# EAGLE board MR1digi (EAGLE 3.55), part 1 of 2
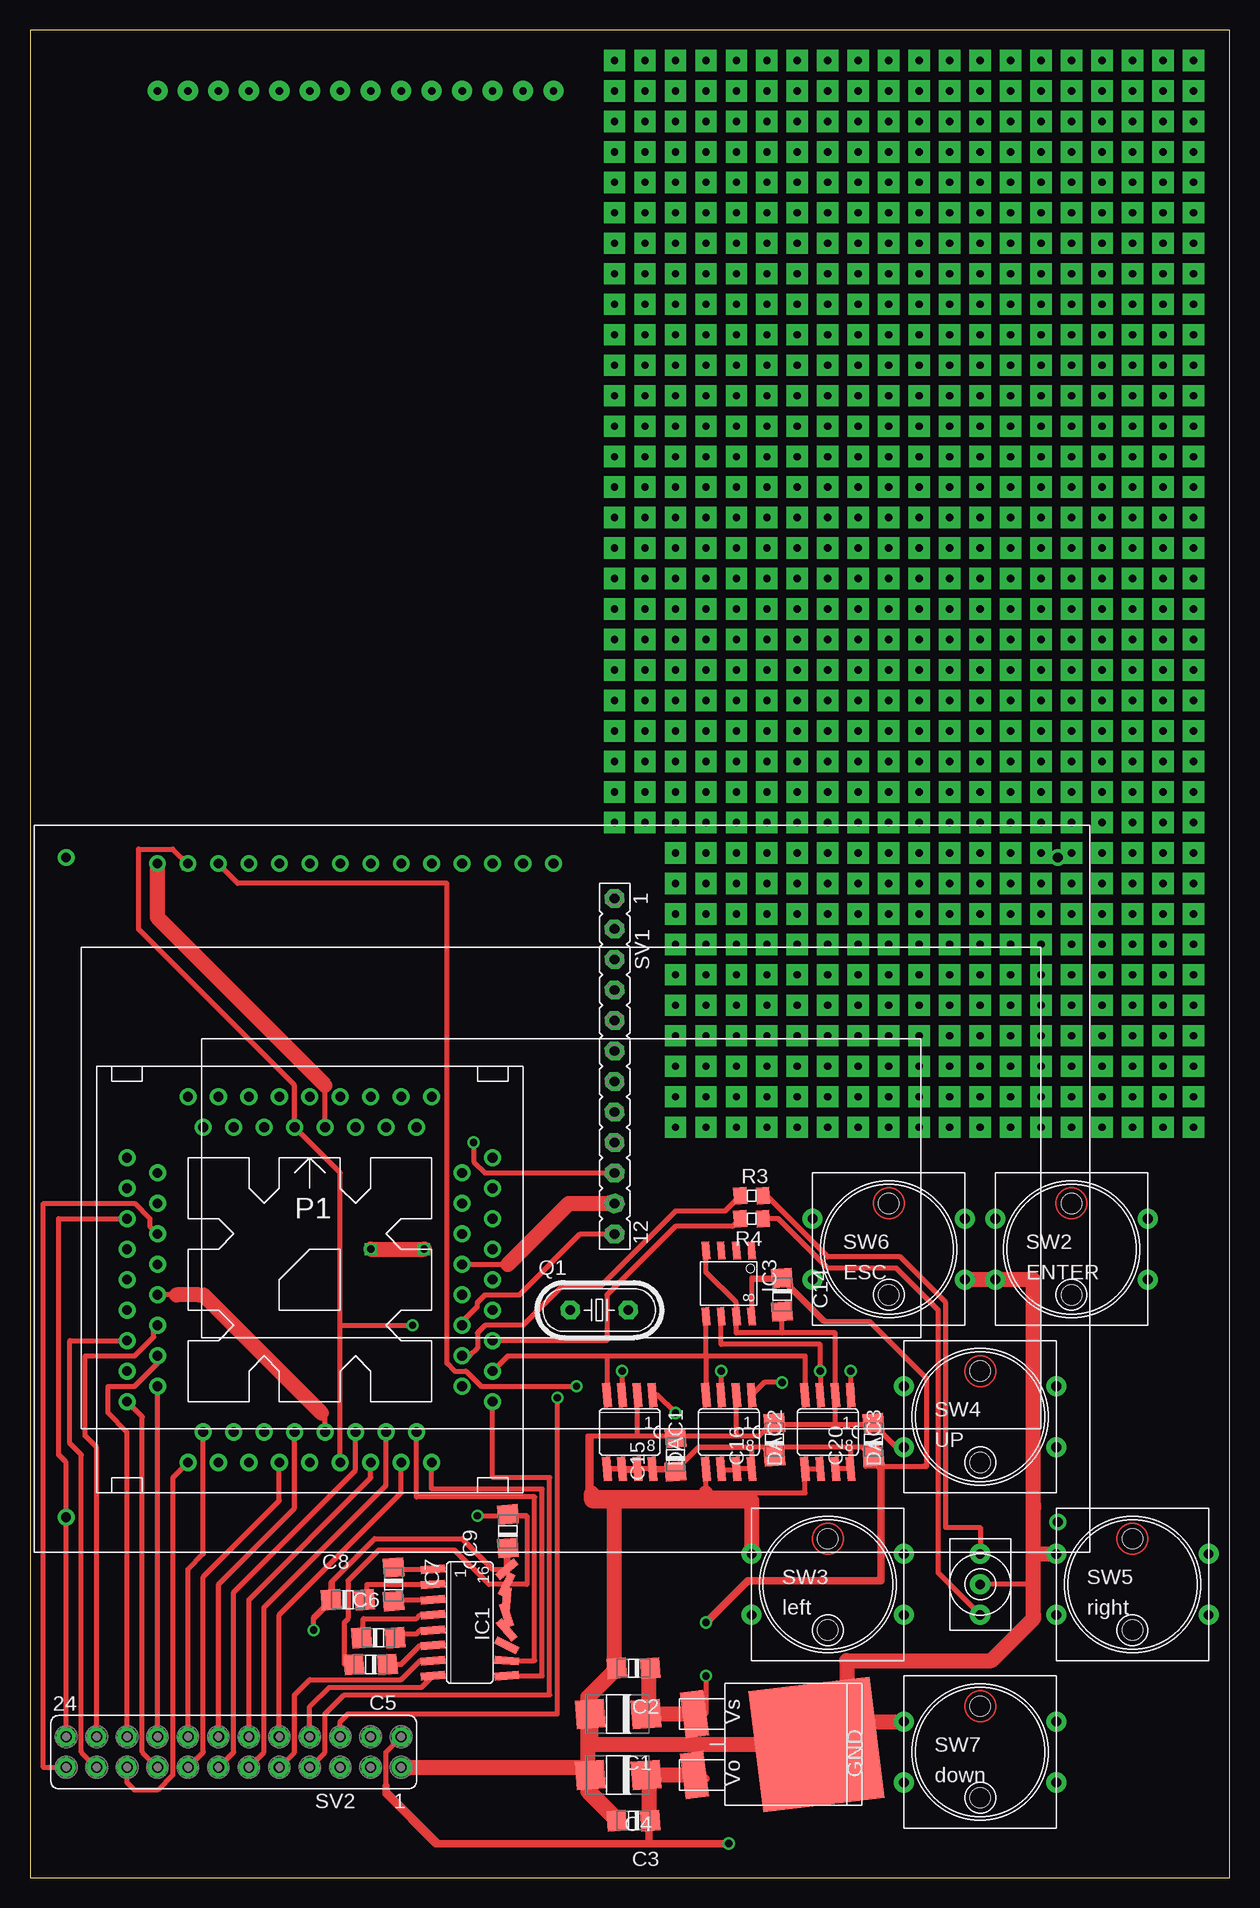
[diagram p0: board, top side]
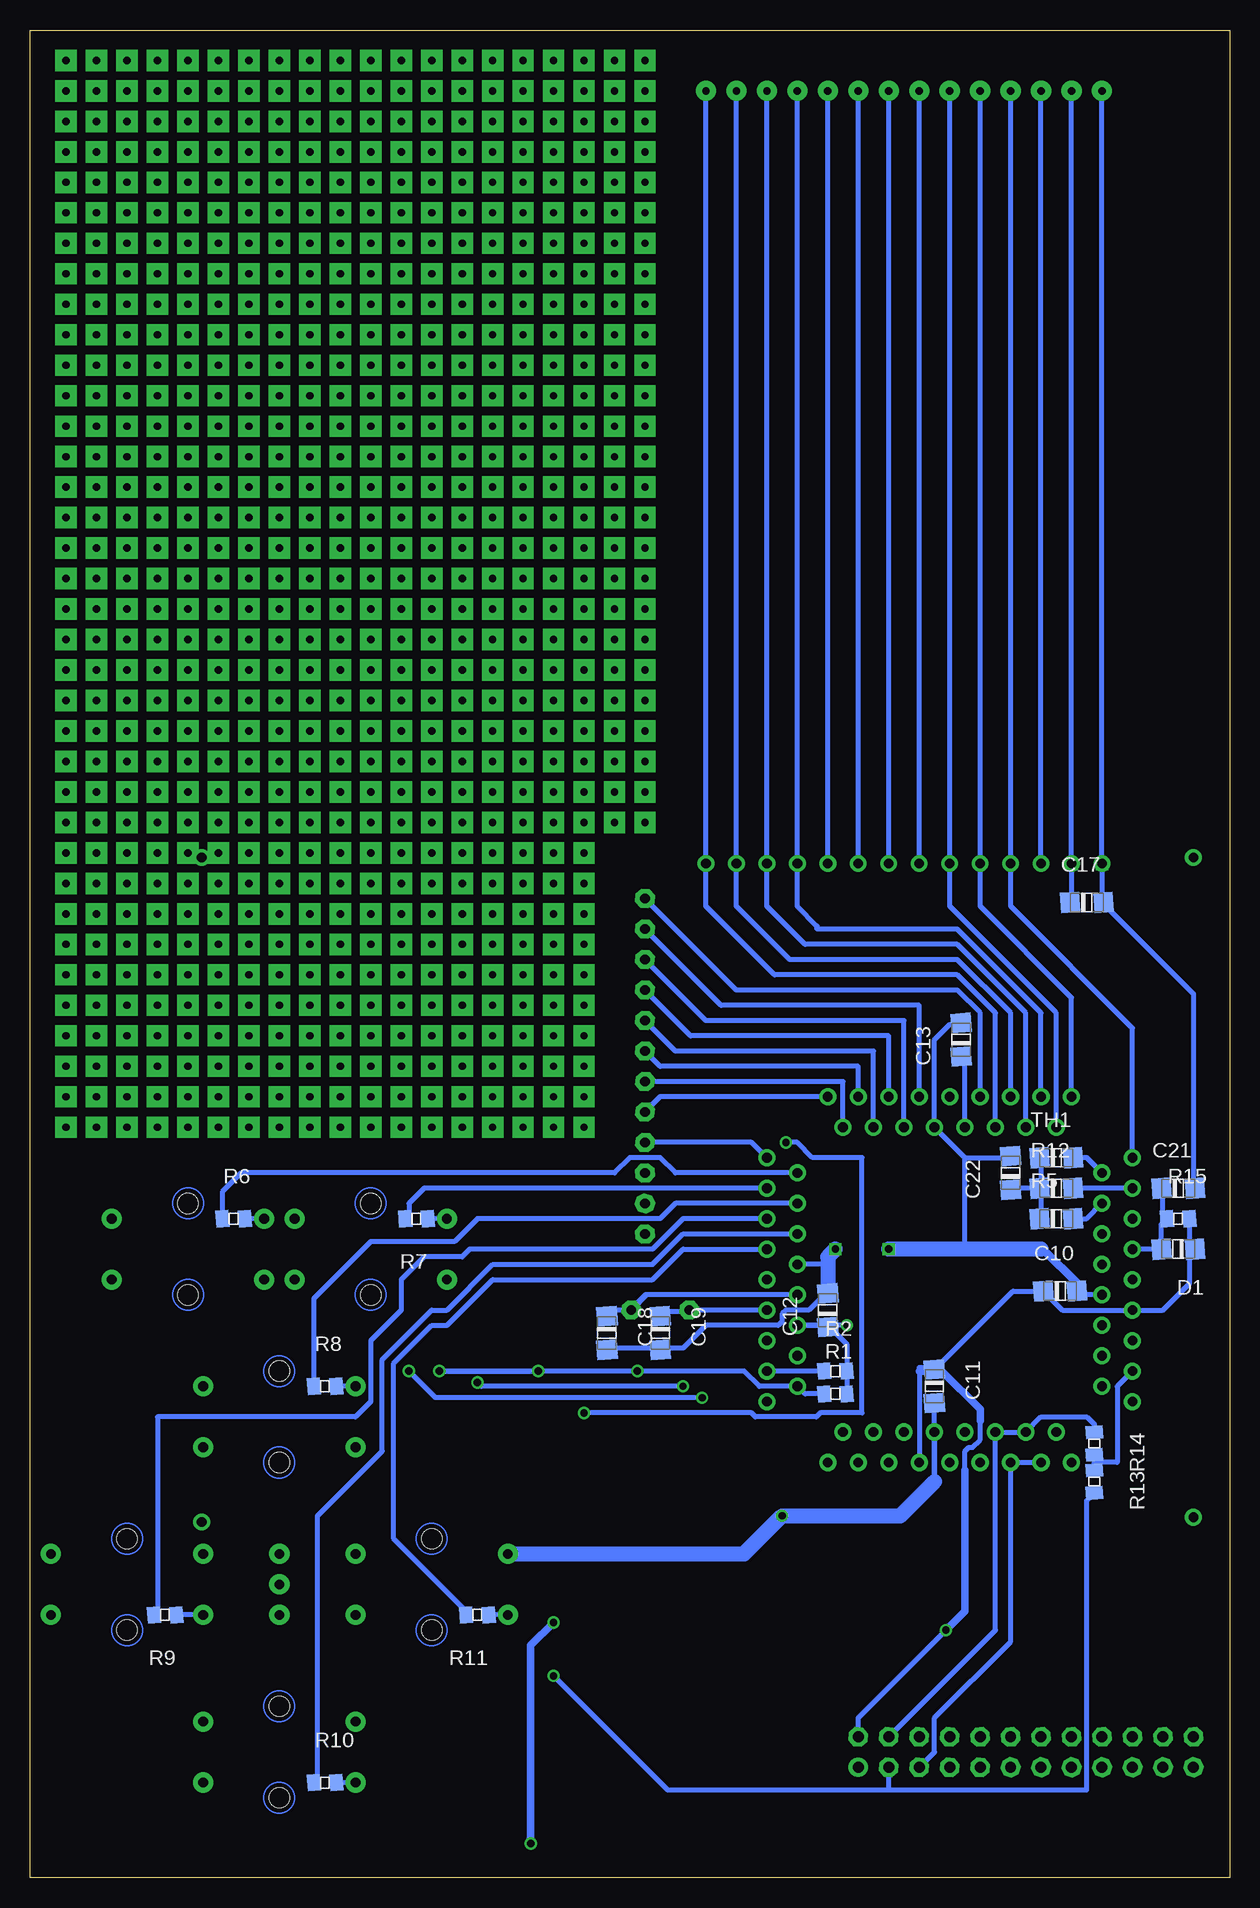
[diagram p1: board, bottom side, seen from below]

Size 100 x 153.98 mm. Coordinates in mm from the lower left corner, seen from the top.
Outline: 0,0 100,0 100,153.98 0,153.98 0,0
Copper layers used: Top, Bottom

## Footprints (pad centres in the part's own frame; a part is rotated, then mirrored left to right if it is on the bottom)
32 = smd 2.388 x 2.388 rotated 4.4:  2.337,0 | smd 2.388 x 2.388 rotated 4.3:  -2.311,0
16 = smd 1.6 x 1.702 rotated 4.4:  1.397,0 | smd 1.6 x 1.702 rotated 4.3:  -1.397,0
08 = smd 0.66 x 2.032 rotated 4.3:  -1.905,-3.073 | smd 0.66 x 2.032 rotated 4.9:  -1.905,3.073 | smd 0.66 x 2.032 rotated 4.4:  -0.635,-3.073 | smd 0.66 x 2.032 rotated 4.5:  0.635,-3.073 | smd 0.66 x 2.032 rotated 4.8:  -0.635,3.073 | smd 0.66 x 2.032 rotated 4.7:  0.635,3.073;  1.905,3.073 | smd 0.66 x 2.032 rotated 4.6:  1.905,-3.073
16' = smd 0.66 x 2.032 rotated 4.3:  -4.445,-3.073;  3.175,3.073 | smd 0.66 x 2.032 rotated 139.3:  -4.445,3.073 | smd 0.66 x 2.032 rotated 4.4:  -3.175,-3.073 | smd 0.66 x 2.032 rotated 4.5:  -1.905,-3.073 | smd 0.66 x 2.032 rotated 116.8:  -3.175,3.073 | smd 0.66 x 2.032 rotated 94.3:  -1.905,3.073 | smd 0.66 x 2.032 rotated 4.6:  -0.635,-3.073 | smd 0.66 x 2.032 rotated 71.8:  -0.635,3.073 | smd 0.66 x 2.032 rotated 4.7:  0.635,-3.073;  1.905,-3.073 | smd 0.66 x 2.032 rotated 49.3:  0.635,3.073 | smd 0.66 x 2.032 rotated 4.8:  3.175,-3.073 | smd 0.66 x 2.032 rotated 26.8:  1.905,3.073 | smd 0.66 x 2.032 rotated 4.9:  4.445,-3.073 | smd 0.66 x 2.032 rotated 5:  4.445,3.073
D_TO22 = smd 1.93 x 3.81 rotated 97:  1.27,-6.35;  6.35,-6.35 | smd 10.16 x 10.16 rotated 97:  3.81,3.81
8 = smd 0.61 x 1.524 rotated 4.3:  -1.27,-2.743 | smd 0.61 x 1.524 rotated 4.9:  -1.27,2.743 | smd 0.61 x 1.524 rotated 4.4:  0,-2.743 | smd 0.61 x 1.524 rotated 4.5:  1.27,-2.743 | smd 0.61 x 1.524 rotated 4.8:  0,2.743 | smd 0.61 x 1.524 rotated 4.7:  1.27,2.743;  2.54,2.743 | smd 0.61 x 1.524 rotated 4.6:  2.54,-2.743
-1604A = drill 0.813 pad 1.397 round: 0 -10.795,27.051; 1 -8.255,27.051; 2 -5.715,27.051; 3 -3.175,27.051; 4 -0.635,27.051; 5 -41.275,27.559; 6 -41.275,-27.432; 7 41.402,-27.813; 8 41.402,27.559;  -33.655,27.051;  -31.115,27.051;  -28.575,27.051;  -26.035,27.051;  -23.495,27.051;  -20.955,27.051;  -18.415,27.051;  -15.875,27.051;  -13.335,27.051
49U-V = drill 0.813 pad 1.6 octagon:  -2.413,0;  2.413,0
05 = smd 1.092 x 1.397 rotated 4.4:  0.94,0 | smd 1.092 x 1.397 rotated 4.3:  -0.94,0
12 = drill 0.813 pad 1.6 octagon:  -13.97,0;  -11.43,0;  -8.89,0;  -6.35,0;  -3.81,0;  -1.27,0;  1.27,0;  3.81,0;  6.35,0;  8.89,0;  11.43,0;  13.97,0
12-2 = drill 0.914 pad 1.6 round:  -13.97,1.27 | drill 0.914 pad 1.6 octagon:  -13.97,-1.27;  -11.43,1.27;  -11.43,-1.27;  -8.89,1.27;  -8.89,-1.27;  -6.35,1.27;  -6.35,-1.27;  -3.81,1.27;  -3.81,-1.27;  -1.27,1.27;  -1.27,-1.27;  1.27,1.27;  1.27,-1.27;  3.81,1.27;  3.81,-1.27;  6.35,1.27;  6.35,-1.27;  8.89,1.27;  8.89,-1.27;  11.43,1.27;  11.43,-1.27;  13.97,1.27;  13.97,-1.27
03 = drill 0.813 pad 1.676 round:  -2.54,0;  0,0;  2.54,0
MR1 = drill 0.813 pad 1.676 round:  -5.08,2.54;  -5.08,-2.54;  7.62,-2.54;  7.62,2.54 | hole 1.676: 1.27,3.81; 1.27,-3.81
F-68 = drill 0.813 pad 1.422 round: 0 -15.24,10.16; 0 -15.24,-2.54; 0 -6.35,-12.7; 0 6.35,-12.7; 0 15.24,-2.54; 0 15.24,10.16; 1 -12.7,8.89; 1 -12.7,-3.81; 1 -5.08,-15.24; 1 7.62,-15.24; 1 12.7,-1.27; 1 10.16,15.24; 2 -15.24,7.62; 2 -15.24,-5.08; 2 -3.81,-12.7; 2 8.89,-12.7; 2 15.24,0; 2 8.89,12.7; 3 -12.7,6.35; 3 -12.7,-6.35; 3 -2.54,-15.24; 3 10.16,-15.24; 3 12.7,1.27; 3 7.62,15.24; 4 -15.24,5.08; 4 -15.24,-7.62; 4 -1.27,-12.7; 4 15.24,-10.16; 4 15.24,2.54; 4 6.35,12.7; 5 -12.7,3.81; 5 -12.7,-8.89; 5 0,-15.24; 5 12.7,-8.89; 5 12.7,3.81; 5 5.08,15.24; 6 -15.24,2.54; 6 -15.24,-10.16; 6 1.27,-12.7; 6 15.24,-7.62; 6 15.24,5.08; 6 3.81,12.7; 7 -12.7,1.27; 7 -10.16,-15.24; 7 2.54,-15.24; 7 12.7,-6.35; 7 12.7,6.35; 7 2.54,15.24; 8 -15.24,0; 8 -8.89,-12.7; 8 3.81,-12.7; 8 15.24,-5.08; 8 15.24,7.62; 8 1.27,12.7; 9 -12.7,-1.27; 9 -7.62,-15.24; 9 5.08,-15.24; 9 12.7,-3.81; 9 12.7,8.89;  0,15.24;  -1.27,12.7;  -2.54,15.24;  -3.81,12.7;  -5.08,15.24;  -6.35,12.7;  -7.62,15.24;  -8.89,12.7;  -10.16,15.24

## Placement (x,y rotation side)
C1  100u  [32]  49.05,13.65 180 top
C2  100n  [16]  50.32,17.46 180 top
C3  100n  [16]  50.32,4.76 180 top
C4  100u  [32]  49.05,8.57 180 top
C5  100n  [16]  28.41,17.77 180 top
C6  100n  [16]  29.04,20 0 top
C7  100n  [16]  30.31,24.44 270 top
C8  100n  [16]  26.5,23.17 0 top
C9  100n  [16]  39.84,28.89 90 top
C10  100n  [16]  14.12,48.89 0 bottom
C11  100n  [16]  24.6,40.95 270 bottom
C12  100n  [16]  33.49,47.3 90 bottom
C13  100n  [16]  22.38,69.84 90 bottom
C14  100n  [16]  62.7,48.57 270 top
C15  100n  [16]  53.81,35.24 90 top
C16  100n  [16]  62.06,36.51 90 top
C17  100n  [16]  11.9,81.28 0 bottom
C18  30p  [16]  51.91,45.4 270 bottom
C19  30p  [16]  47.46,45.4 270 bottom
C20  100n  [16]  70.32,36.51 90 top
C21  100n  [16]  4.28,57.46 0 bottom
C22  330n  [16]  18.25,58.73 90 bottom
D1  DIODE_3216  [16]  4.28,52.38 180 bottom
DAC1  MAX517BCSA  [08]  50,37.14 180 top
DAC2  MAX517BCSA  [08]  58.25,37.14 180 top
DAC3  MAX517BCSA  [08]  66.51,37.14 180 top
IC1  MAX232CSE  [16']  36.66,21.27 270 top
IC2  MC7805CD2T  [D_TO22]  61.75,14.92 270 top
IC3  24LC04B/08  [8]  58.89,49.53 180 top
LCD1  PC-1604A  [-1604A]  44.28,57.46 0 top
Q1  32MHz  [49U-V]  47.46,47.3 0 top
R1  10k  [05]  32.85,40.32 0 bottom
R2  10k  [05]  32.85,42.22 0 bottom
R3  100  [05]  60.16,54.92 0 top
R4  100  [05]  60.16,56.83 180 top
R5  400  [16]  14.44,54.92 0 bottom
R6  100  [05]  83.02,54.92 0 bottom
R7  100  [05]  67.78,54.92 180 bottom
R8  100  [05]  75.4,40.95 0 bottom
R9  100  [05]  88.73,21.9 180 bottom
R10  100  [05]  75.4,7.93 0 bottom
R11  100  [05]  62.7,21.9 180 bottom
R12  10k  [16]  14.44,57.46 0 bottom
R13  47k  [05]  11.27,33.02 270 bottom
R14  10k  [05]  11.27,36.19 270 bottom
R15  10k  [05]  4.28,54.92 0 bottom
SV1  FE12-1  [12]  48.73,67.62 270 top
SV2  FE12-2  [12-2]  16.98,10.47 180 top
SW1  ET03  [03]  79.21,24.44 90 top
SW2  ENTER  [MR1]  85.56,52.38 0 top
SW3  left  [MR1]  65.24,24.44 0 top
SW4  UP  [MR1]  77.94,38.41 0 top
SW5  right  [MR1]  90.64,24.44 0 top
SW6  ESC  [MR1]  70.32,52.38 0 top
SW7  down  [MR1]  77.94,10.47 0 top
TH1  10k  [16]  14.44,60 0 bottom
UC1  17C75X_ZIF  [F-68]  23.33,49.84 0 top

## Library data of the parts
C1-C22 D1 R1-R15 TH1 = SMD
DAC1-DAC3 IC1 = MAXIM
IC2 = MOTOROLA
IC3 = Microcip
LCD1 = LCDdispl
Q1 = QUARTZ
SV1 SV2 = CON-LSTA
SW1 = SWITCH
SW2-SW7 = KEY
UC1 = PIC

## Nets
+5V/1: SV2. UC1.1 UC1.9
+5V/4: SV2. UC1.4
+UB: C1. C2. IC2. R13. SV2.
AGND: R14. SV2. UC1.0 UC1.2
DGND: C1. C2. C3. C4. C5. C9. C10. C11. C12. C13. C14. C15. C16. C17. C18. C19. C20. C21. C22. DAC1. DAC2. DAC3. IC1. IC2. IC3. LCD1. SV1. SV2. SW1. SW2. SW3. SW4. SW5. SW6. SW7. UC1.3 UC1.6 UC1.8 UC1.9
N$1: C7. IC1.
N$2: IC1. UC1.3
N$3: IC1. UC1.2
N$4: C7. IC1.
N$5: C6. IC1.
N$6: C6. IC1.
N$7: C5. IC1.
N$8: C8. IC1.
N$10: IC1. SV2.
N$11: DAC1. DAC2. DAC3. IC3. R2. UC1.6
N$12: DAC1. DAC2. DAC3. IC3. R1. UC1.5
N$13: LCD1.4 UC1.
N$14: LCD1.3 UC1.
N$15: LCD1.2 UC1.
N$16: LCD1.1 UC1.
N$17: LCD1. UC1.
N$18: LCD1. UC1.
N$19: LCD1. UC1.0
N$20: DAC2. LCD1.
N$21: R3. SW1.
N$22: R4. SW1.
N$23: DAC1. SV1.
N$24: R7. SW6.
N$25: R6. SW2.
N$26: R8. SW4.
N$27: R10. SW7.
N$28: R11. SW3.
N$29: R9. SW5.
N$30: R6. UC1.9
N$31: R7. UC1.8
N$32: R8. UC1.7
N$33: R9. UC1.6
N$34: R10. UC1.5
N$35: R11. UC1.4
N$36: C18. Q1. UC1.1
N$37: C19. Q1. UC1.0
N$38: TH1. UC1.1
N$39: R12. UC1.2
N$40: R5. UC1.3
N$41: SV2. UC1.7
N$42: SV1. UC1.
N$43: SV2. UC1.8
N$44: SV2. UC1.6
N$45: SV2. UC1.5
N$47: SV2. UC1.3
N$48: SV2. UC1.2
N$49: SV2. UC1.1
N$50: SV2. UC1.5
N$52: SV2. UC1.3
N$53: SV2. UC1.4
N$54: SV2. UC1.8
N$55: SV2. UC1.9
N$56: SV2. UC1.0
N$57: SV2. UC1.1
N$58: SV1. UC1.7
N$59: SV1. UC1.6
N$60: SV1. UC1.5
N$61: SV1. UC1.4
N$62: SV1. UC1.3
N$63: SV1. UC1.2
N$64: SV1. UC1.1
N$65: SV1. UC1.0
N$67: SV2. UC1.4
N$68: DAC3. SV2.
N$69: C21. D1. R15. UC1.6
N$86: IC1. SV2.
N$719: C22. R5. R12. TH1.
N$720: R3. UC1.8
N$721: R4. UC1.7
N$722: R13. R14. UC1.4
VDD: C3. C4. C8. C9. C10. C11. C12. C13. C14. C15. C16. C17. C20. D1. DAC1. DAC2. DAC3. IC1. IC2. IC3. LCD1. R1. R2. R15. SV1. SV2. UC1. UC1.0 UC1.7 UC1.9

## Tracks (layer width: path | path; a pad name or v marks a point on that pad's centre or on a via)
+5V/1
  Bottom 0.406: 25.87,9.2 24.6,10.47 24.6,13.33 18.25,19.68 18.25,34.6 15.71,34.6
+5V/4
  Top 0.406: 8.09,54.92 2.38,54.92 2.38,35.24 3.01,34.6 SV2.
+UB  (via drill 0.61 pad 1.02)
  Top 0.406: v56.35,16.82 56.35,13.65 C1. 51.27,13.65
  Top 1.27: 51.59,13.65 55.4,13.65 | C1. 51.59,13.65 | C2. 51.59,17.33 51.59,13.65
  Bottom 0.406: 28.41,7.3 11.9,7.3 11.9,31.43 11.27,32.06 11.27,32.08 | 28.41,7.3 28.41,9.2 | 28.41,7.3 46.82,7.3 v56.35,16.82
AGND
  Bottom 0.406: 19.52,37.14 16.98,37.14 | 28.41,11.74 19.52,20.63 19.52,37.14 | 19.52,37.14 16.98,37.14 | R14. 11.27,37.78 11.9,38.41 15.71,38.41 16.98,37.14
DGND  (via drill 0.61 pad 1.02, 0.61 pad 1.68)
  Top 0.406: 62.06,37.9 61.94,37.78 61.75,37.78 | 67.14,37.78 67.14,40.22 | 56.35,32.06 DAC2. | 58.89,40.32 58.89,40.22 58.89,36.83 | DAC3. 65.88,34.07 | 65.88,34.07 65.88,33.97 | DAC3. 65.88,34.07 | DAC3. 64.61,32.06 56.35,32.06 | 56.35,32.06 46.82,32.06 46.82,36.83 | 58.89,45.4 58.89,46.67 | 62.7,45.4 58.89,45.4 | 50.63,40.32 50.63,40.22 50.63,36.83 | 62.7,45.4 62.7,47.18 | 67.14,45.4 62.7,45.4 | 70.32,37.9 70.19,37.78 67.14,37.78 | 58.89,46.67 58.89,46.78 | 58.89,46.67 58.89,47.94 | 41.43,24.44 39.84,24.44 | 39.84,30.28 39.84,30.16 41.43,30.16 | 27.14,17.77 27.01,17.77 26.19,17.77 26.19,21.27 26.5,21.58 26.5,24.76 29.04,27.3 35.39,27.3 38.25,24.44 | 39.84,24.44 39.74,24.44 | 39.84,24.44 38.25,24.44 | 53.81,36.83 58.89,36.83 | 58.89,36.83 60.8,36.83 | 72.86,35.87 72.22,35.87 70.32,37.78 67.14,37.78 | 46.82,31.74 48.73,31.74 48.73,31.43 48.73,17.14 | 48.73,17.14 48.73,17.46 | 48.73,17.14 46.82,15.24 46.82,11.11 67.46,11.11 | 83.66,31.11 83.64,31.1 | 77.94,49.84 80.48,49.84 | 46.51,14.92 48.73,17.14 | 46.51,11.11 68.1,11.11 68.1,18.09 | 39.84,51.11 36.03,51.11 40.16,51.11 45.24,56.19 48.73,56.19 | UC1.8 24.6,66.04 | 24.6,38.41 24.28,38.73 | 12.22,48.57 10.63,48.57 14.12,48.57 24.6,38.09 24.6,37.14 24.6,38.41 | v37.3,30.16 41.43,30.16 | 41.43,30.16 41.43,24.44 | 41.43,24.44 38.25,24.44 | 56.35,52.27 56.35,50.48 58.89,47.94 | 58.89,45.4 58.89,47.94 | 67.14,45.4 58.89,45.4 | 67.14,37.78 67.14,45.4 | 61.75,37.78 67.14,37.78 | 60.8,36.83 61.75,37.78 | 53.81,36.83 60.8,36.83 | 50.63,36.83 53.81,36.83 | 46.82,36.83 50.63,36.83 | 46.82,31.74 46.82,36.83 | 24.6,38.41 14.44,48.57 | 60.16,31.43 59.84,31.74 46.82,31.74 | 46.82,31.74 46.51,32.06 46.51,36.83 50.63,36.83
  Top 0.406: 53.81,36.83 53.81,36.63 | 79.21,24.44 83.66,24.44 83.66,30.79 | v28.41,52.38 v32.85,52.38 v28.41,52.38
  Top 1.27: 46.51,8.57 46.71,8.57 | 46.71,13.65 46.51,13.44 46.51,11.11 | 46.51,8.57 46.51,7.17 48.92,4.76 49.05,4.76 46.51,7.3 46.51,8.57 | 46.71,13.65 46.51,13.65 46.51,11.11 | 48.92,17.46 46.51,15.04 46.51,14.92 46.51,11.11 | 46.51,9.2 46.51,8.57 | 46.51,9.2 46.51,11.11 | 46.71,13.65 46.71,11.11 46.82,11.11 IC2. 65.56,11.43 67.14,13.01 72.86,13.01 | 30.95,9.2 46.51,9.2 | 83.66,26.98 85.56,26.98 | 46.82,32.06 46.82,31.74 46.82,31.43 | 48.73,31.43 56.35,31.43 | 48.73,31.43 46.82,31.43 | 56.35,31.43 56.35,32.06 | 56.35,31.43 59.84,31.43 | 59.84,31.43 60.16,31.43 | 48.73,31.43 59.84,31.43 | 48.73,17.46 48.73,31.43 | 83.66,26.98 83.66,30.79 | 83.66,21.9 83.66,26.98 | 67.46,11.11 67.46,13.96 68.1,13.96 68.1,18.09 80.16,18.09 83.66,21.58 83.66,21.9 | 77.94,49.84 83.66,49.84 83.66,31.11 83.66,30.79 | 83.66,21.9 83.66,30.79 | 39.84,51.11 44.92,56.19 48.73,56.19 | 24.6,66.04 10.63,80 v10.63,84.45 | v28.41,52.38 v32.85,52.38 | 24.28,38.73 14.44,48.57 14.12,48.57 12.22,48.57 | 60.16,31.43 60.16,26.98 | 46.82,31.43 60.16,31.43
  Bottom 0.406: 47.46,44.13 47.46,44 | 10.63,81.28 10.5,81.28 | 10.63,84.51 v10.63,84.45 10.63,84.13 | 24.6,39.68 24.6,39.56 24.6,37.14 | 12.85,49.53 12.85,48.89 12.73,48.89 12.41,48.57 10.63,48.57 12.54,48.57 | 22.38,71.24 22.5,71.12 23.33,71.12 24.6,69.84 UC1.8 22.06,60 | 33.49,48.7 33.49,48.89 35.08,47.3 36.98,47.3 37.3,46.98 37.3,46.35 37.62,46.03 43.65,46.03 45.55,44.13 47.46,44.13 | 12.54,48.57 12.85,48.57 12.85,49.53 | 15.71,52.38 12.85,49.53 | 10.63,84.13 10.63,81.28 | 2.88,57.46 3.01,57.46 3.01,73.65 10.63,81.28 | 24.6,37.14 24.6,33.01 | 12.54,48.57 12.54,49.53 15.39,52.38 15.71,52.38 | 33.49,51.11 36.03,51.11 | 51.91,44 51.78,44.13 47.46,44.13 | 15.71,52.38 12.54,49.21 12.54,48.57 | 24.6,37.14 24.6,33.33 27.77,30.16 | 10.63,84.13 v10.63,148.9 | 18.25,60.13 18.25,60 22.06,60 | 22.06,52.38 22.06,60
  Bottom 1.27: 15.71,52.38 22.06,52.38 v28.41,52.38 | v32.85,52.38 33.49,51.75 33.49,51.11 33.49,48.89 | 60.16,26.98 40.48,26.98 v37.3,30.16 27.77,30.16 27.46,30.16 24.6,33.01
N$1
  Top 0.406: C7. 30.31,25.71 33.59,25.71
N$2
  Top 0.406: 33.49,34.6 33.49,32.38 42.7,32.38 42.7,16.82 IC1.
N$3
  Top 0.406: 32.22,37.14 32.22,31.74 42.06,31.74 42.06,18.09 39.74,18.09
N$4
  Top 0.406: 30.31,23.05 30.44,23.17 33.59,23.17
N$5
  Top 0.406: 33.59,21.9 32.54,21.9 32.22,21.58 27.77,21.58 27.77,20 C6.
N$6
  Top 0.406: 33.59,20.63 32.54,20.63 32.22,20.31 30.63,20.31 30.63,20.19 30.44,20
N$7
  Top 0.406: 33.59,19.36 32.54,19.36 30.95,17.77 C5.
N$8
  Top 0.406: 33.59,24.44 28.09,24.44 28.09,23.17 27.9,23.17
N$9  (via drill 0.61 pad 1.78)
  other vias: 53.81,82.86
N$10
  Top 0.406: 33.59,18.09 32.54,18.09 30.95,16.51 23.33,16.51 22.06,15.24 22.06,10.47 20.79,9.2
N$11
  Top 0.406: 56.35,43.49 56.35,40.22 | 64.61,40.22 64.61,43.49 56.35,43.49 | 48.09,43.49 39.84,43.49 38.57,42.22 | 48.09,43.49 48.09,40.22 | 48.09,43.49 56.35,43.49 | 56.35,43.49 IC3.
  Bottom 0.406: R2. 38.57,42.22 R2. | R2. 33.49,42.22
N$12  (via drill 0.61 pad 1.02)
  Top 0.406: 65.88,40.22 v65.88,42.22 65.88,44.44 57.62,44.44 57.62,46.78 | v57.62,42.22 57.62,40.22 | v49.37,42.22 49.37,40.22
  Bottom 0.406: v65.88,42.22 v57.62,42.22 | 40.48,42.22 v49.37,42.22 | 33.49,40.32 R1. 35.39,40.32 36.03,40.95 39.2,40.95 40.48,42.22 | v49.37,42.22 v57.62,42.22 | v49.37,42.22 v57.62,42.22 | v65.88,42.22 v57.62,42.22 | 40.48,42.22 v65.88,42.22
N$13  (via drill 0.61 pad 1.68)
  Bottom 0.406: 19.52,62.54 19.52,72.07 22.7,75.24 37.94,75.24 43.65,80.96 43.65,84.13 | 43.65,84.13 LCD1.4 | 43.65,84.13 v43.65,148.9
N$14  (via drill 0.61 pad 1.68)
  Bottom 0.406: 18.25,65.08 18.25,72.07 22.7,76.51 36.66,76.51 41.11,80.96 41.11,84.13 | 41.11,84.13 LCD1.3 | 41.11,84.13 v41.11,148.9
N$15  (via drill 0.61 pad 1.68)
  Bottom 0.406: 16.98,62.54 16.98,72.07 22.7,77.78 35.39,77.78 38.57,80.96 38.57,82.86 | 38.57,82.86 LCD1.2 | 38.57,82.86 v38.57,148.9
N$16  (via drill 0.61 pad 1.68)
  Bottom 0.406: 15.71,65.08 15.71,72.07 22.7,79.05 34.38,79.05 34.38,79.31 36.03,80.96 36.03,84.13 | 36.03,84.13 LCD1.1 | 36.03,84.13 v36.03,148.9
N$17  (via drill 0.61 pad 1.68)
  Bottom 0.406: 14.44,62.54 14.44,72.07 23.33,80.96 23.33,84.13 | 23.33,84.13 23.33,84.51 | 23.33,84.13 v23.33,148.9
N$18  (via drill 0.61 pad 1.68)
  Bottom 0.406: 20.79,84.13 20.79,80.96 13.17,73.34 UC1. | 20.79,84.13 20.79,84.51 | 20.79,84.13 v20.79,148.9
N$19  (via drill 0.61 pad 1.68)
  Bottom 0.406: 18.25,84.13 18.25,80.96 8.09,70.8 8.09,60 | 18.25,84.13 18.25,84.51 | 18.25,84.13 v18.25,148.9
N$20  (via drill 0.61 pad 1.02)
  Top 0.406: 60.16,40.22 61.21,41.27 v62.7,41.27 | v45.55,40.95 37.62,40.95 36.35,42.22 35.39,42.22 34.76,42.86 34.76,82.86 17.3,82.86 15.71,84.45 15.71,84.51
  Bottom 0.406: v62.7,41.27 62.38,40.95 v45.55,40.95
N$21
  Top 0.406: 79.21,21.9 75.72,25.4 75.72,47.3 72.22,50.79 66.51,50.79 62.38,54.92 61.1,54.92 60.8,54.92
N$22
  Top 0.406: SW1. 79.21,29.2 76.35,29.2 76.35,47.94 72.54,51.75 66.51,51.75 61.43,56.83 R4.
N$23  (via drill 0.61 pad 1.02)
  Top 0.406: 51.91,40.22 52.32,40.22 v53.81,38.73 | v36.98,61.27 36.98,59.68 37.94,58.73 48.73,58.73
  Bottom 0.406: v53.81,38.73 39.84,38.73 39.52,38.41 34.44,38.41 34.12,38.73 30.63,38.73 30.63,60 34.76,60 36.03,61.27 v36.98,61.27
N$24
  Bottom 0.406: 67.14,54.92 R7. 65.24,54.92
N$25
  Bottom 0.406: 80.48,54.92 82.08,54.92
N$26
  Bottom 0.406: 72.86,40.95 74.46,40.95
N$27
  Bottom 0.406: 72.86,7.93 74.46,7.93
N$28
  Bottom 0.406: 60.16,21.9 R11.
N$29
  Bottom 0.406: 85.56,21.9 R9.
N$30
  Bottom 0.406: R6. 83.96,57.16 82.39,58.73 51.27,58.73 50,60 47.46,60 46.19,58.73 UC1.9
N$31
  Bottom 0.406: 38.57,57.46 67.14,57.46 68.41,56.19 68.41,54.92 68.72,54.92
N$32
  Bottom 0.406: R8. 76.34,48.27 71.59,53.02 64.61,53.02 62.7,54.92 47.46,54.92 46.19,56.19 36.03,56.19
N$33
  Bottom 0.406: 89.67,21.9 89.37,21.9 89.37,38.41 72.86,38.41 71.59,39.68 71.59,44.76 69.05,47.3 69.05,49.84 67.14,51.75 63.97,51.75 63.34,52.38 48.09,52.38 45.55,54.92 38.57,54.92
N$34
  Bottom 0.406: R10. 76.03,7.93 76.03,30.16 70.64,35.56 70.64,43.18 66.51,47.3 65.24,47.3 61.43,51.11 48.09,51.11 45.55,53.65 36.03,53.65
N$35
  Bottom 0.406: 63.64,21.9 63.34,21.9 69.69,28.25 69.69,42.86 66.51,46.03 65.24,46.03 61.43,49.84 48.09,49.84 45.55,52.38 38.57,52.38
N$36
  Bottom 0.406: C18. 51.4,47.3 50,47.3 48.73,48.57 36.03,48.57 48.6,48.57 Q1.
N$37
  Bottom 0.406: 47.46,46.67 C19. 47.46,47.18 44.92,47.18 44.92,47.3 38.57,47.3 45.05,47.3
N$38
  Bottom 0.406: 13.17,60 13.04,60 11.9,60 10.63,58.73
N$39
  Bottom 0.406: 13.17,57.46 13.04,57.46 8.09,57.46
N$40
  Bottom 0.406: 13.17,54.92 13.04,54.92 11.9,54.92 10.63,56.19
N$41
  Top 0.406: 13.17,34.6 11.9,33.33 11.9,8.57 10.63,7.3 8.73,7.3 8.09,7.93 8.09,9.2
N$42
  Bottom 0.406: 20.79,65.08 20.79,72.07 22.7,73.97 41.11,73.97 48.73,81.59
N$43
  Top 0.406: 13.17,11.74 13.17,25.71 14.44,26.98 14.44,37.14
N$44
  Top 0.406: 10.63,9.2 9.36,10.47 9.36,38.41 8.09,39.68
N$45
  Top 0.406: 10.63,11.74 10.63,40.95
N$47
  Top 0.406: 8.09,11.74 8.09,37.14 6.5,38.73 6.5,40.95 8.73,40.95 10.63,42.86 10.63,43.49
N$48
  Top 0.406: 5.55,9.2 4.28,10.47 4.28,35.24 3.33,36.19 3.33,44.76 8.09,44.76
N$49
  Top 0.406: 5.55,11.74 5.55,35.87 4.6,36.83 4.6,43.49 8.73,43.49 10.31,45.08 10.31,45.72 10.63,46.03
N$50
  Top 0.406: 3.01,9.2 1.1,9.2 1.1,56.19 8.73,56.19 10,54.92 10,54.29 10.63,53.65
N$51  (via drill 0.61 pad 1.78)
  other vias: 53.81,80.32
N$52
  Top 0.406: 13.17,9.2 14.44,10.47 14.44,25.08 20.79,31.43 20.79,34.6
N$53
  Top 0.406: 15.71,11.74 15.71,24.44 22.06,30.79 22.06,37.14
N$54
  Top 0.406: 15.71,9.2 16.98,10.47 16.98,23.81 27.14,33.97 27.14,37.14
N$55
  Top 0.406: 18.25,11.74 18.25,23.17 28.41,33.33 28.41,34.6
N$56
  Top 0.406: 18.25,9.2 19.52,10.47 19.52,22.54 29.68,32.7 29.68,37.14
N$57
  Top 0.406: 20.79,11.74 20.79,21.9 30.95,32.06 30.95,34.6
N$58
  Bottom 0.406: UC1.7 25.87,72.7 42.38,72.7 48.73,79.05
N$59
  Bottom 0.406: UC1.6 27.14,71.43 43.65,71.43 48.73,76.51
N$60
  Bottom 0.406: UC1.5 28.41,70.16 44.92,70.16 48.73,73.97
N$61
  Bottom 0.406: UC1.4 29.68,68.89 46.19,68.89 48.73,71.43
N$62
  Bottom 0.406: UC1.3 30.95,67.62 47.46,67.62 48.73,68.89
N$63
  Bottom 0.406: UC1.2 32.22,66.35 48.73,66.35
N$64
  Bottom 0.406: UC1.1 47.46,65.08 48.73,63.81
N$65
  Bottom 0.406: 48.73,61.27 39.84,61.27 UC1.0
N$66  (via drill 0.61 pad 1.78)
  other vias: 53.81,77.78
N$67
  Top 0.406: 38.57,39.68 38.57,33.33 43.33,33.33 43.33,15.24 26.19,15.24 24.6,13.65 24.6,10.47 23.33,9.2
N$68  (via drill 0.61 pad 1.02)
  Top 0.406: 25.87,11.74 25.87,13.01 26.5,13.65 43.97,13.65 v43.97,40 | v68.41,42.22 68.41,40.22
  Bottom 0.406: v68.41,42.22 66.19,40 v43.97,40
N$69
  Bottom 0.406: 8.09,52.38 5.68,52.38 5.68,54.48 5.23,54.92 R15. 5.55,55.25 5.55,57.46 C21.
N$70  (via drill 0.61 pad 1.78)
  other vias: 53.81,85.4
N$71  (via drill 0.61 pad 1.78)
  other vias: 53.81,75.24
N$72  (via drill 0.61 pad 1.78)
  other vias: 53.81,72.7
N$73  (via drill 0.61 pad 1.78)
  other vias: 53.81,70.16
N$74  (via drill 0.61 pad 1.78)
  other vias: 53.81,67.62
N$75  (via drill 0.61 pad 1.78)
  other vias: 53.81,65.08
N$76  (via drill 0.61 pad 1.78)
  other vias: 53.81,62.54
N$77  (via drill 0.61 pad 1.78)
  other vias: 56.35,62.54
N$78  (via drill 0.61 pad 1.78)
  other vias: 56.35,65.08
N$79  (via drill 0.61 pad 1.78)
  other vias: 56.35,67.62
N$80  (via drill 0.61 pad 1.78)
  other vias: 56.35,70.16
N$81  (via drill 0.61 pad 1.78)
  other vias: 56.35,72.7
N$82  (via drill 0.61 pad 1.78)
  other vias: 56.35,75.24
N$83  (via drill 0.61 pad 1.78)
  other vias: 56.35,77.78
N$84  (via drill 0.61 pad 1.78)
  other vias: 56.35,80.32
N$85  (via drill 0.61 pad 1.78)
  other vias: 56.35,82.86
N$86
  Top 0.406: 33.59,16.82 32.64,15.87 24.92,15.87 23.33,14.28 23.33,11.74
N$87  (via drill 0.61 pad 1.78)
  other vias: 56.35,85.4
N$88  (via drill 0.61 pad 1.78)
  other vias: 58.89,85.4
N$89  (via drill 0.61 pad 1.78)
  other vias: 58.89,82.86
N$90  (via drill 0.61 pad 1.78)
  other vias: 58.89,80.32
N$91  (via drill 0.61 pad 1.78)
  other vias: 58.89,77.78
N$92  (via drill 0.61 pad 1.78)
  other vias: 58.89,75.24
N$93  (via drill 0.61 pad 1.78)
  other vias: 58.89,72.7
N$94  (via drill 0.61 pad 1.78)
  other vias: 58.89,70.16
N$95  (via drill 0.61 pad 1.78)
  other vias: 58.89,67.62
N$96  (via drill 0.61 pad 1.78)
  other vias: 58.89,65.08
N$97  (via drill 0.61 pad 1.78)
  other vias: 58.89,62.54
N$98  (via drill 0.61 pad 1.78)
  other vias: 61.43,62.54
N$99  (via drill 0.61 pad 1.78)
  other vias: 61.43,65.08
N$100  (via drill 0.61 pad 1.78)
  other vias: 61.43,67.62
N$101  (via drill 0.61 pad 1.78)
  other vias: 61.43,70.16
N$102  (via drill 0.61 pad 1.78)
  other vias: 61.43,72.7
N$103  (via drill 0.61 pad 1.78)
  other vias: 61.43,75.24
N$104  (via drill 0.61 pad 1.78)
  other vias: 61.43,77.78
N$105  (via drill 0.61 pad 1.78)
  other vias: 61.43,80.32
N$106  (via drill 0.61 pad 1.78)
  other vias: 61.43,82.86
N$107  (via drill 0.61 pad 1.78)
  other vias: 61.43,85.4
N$108  (via drill 0.61 pad 1.78)
  other vias: 63.97,82.86
N$109  (via drill 0.61 pad 1.78)
  other vias: 63.97,80.32
N$110  (via drill 0.61 pad 1.78)
  other vias: 63.97,77.78
N$111  (via drill 0.61 pad 1.78)
  other vias: 63.97,85.4
N$112  (via drill 0.61 pad 1.78)
  other vias: 63.97,75.24
N$113  (via drill 0.61 pad 1.78)
  other vias: 63.97,72.7
N$114  (via drill 0.61 pad 1.78)
  other vias: 63.97,70.16
N$115  (via drill 0.61 pad 1.78)
  other vias: 63.97,67.62
N$116  (via drill 0.61 pad 1.78)
  other vias: 63.97,65.08
N$117  (via drill 0.61 pad 1.78)
  other vias: 63.97,62.54
N$118  (via drill 0.61 pad 1.78)
  other vias: 66.51,62.54
N$119  (via drill 0.61 pad 1.78)
  other vias: 66.51,65.08
N$120  (via drill 0.61 pad 1.78)
  other vias: 66.51,67.62
N$121  (via drill 0.61 pad 1.78)
  other vias: 66.51,70.16
N$122  (via drill 0.61 pad 1.78)
  other vias: 66.51,72.7
N$123  (via drill 0.61 pad 1.78)
  other vias: 66.51,75.24
N$124  (via drill 0.61 pad 1.78)
  other vias: 66.51,77.78
N$125  (via drill 0.61 pad 1.78)
  other vias: 66.51,80.32
N$126  (via drill 0.61 pad 1.78)
  other vias: 66.51,82.86
N$127  (via drill 0.61 pad 1.78)
  other vias: 66.51,85.4
N$128  (via drill 0.61 pad 1.78)
  other vias: 69.05,85.4
N$129  (via drill 0.61 pad 1.78)
  other vias: 69.05,82.86
N$130  (via drill 0.61 pad 1.78)
  other vias: 69.05,80.32
N$131  (via drill 0.61 pad 1.78)
  other vias: 69.05,77.78
N$132  (via drill 0.61 pad 1.78)
  other vias: 69.05,75.24
N$133  (via drill 0.61 pad 1.78)
  other vias: 69.05,72.7
N$134  (via drill 0.61 pad 1.78)
  other vias: 69.05,70.16
N$135  (via drill 0.61 pad 1.78)
  other vias: 69.05,67.62
N$136  (via drill 0.61 pad 1.78)
  other vias: 69.05,65.08
N$137  (via drill 0.61 pad 1.78)
  other vias: 69.05,62.54
N$138  (via drill 0.61 pad 1.78)
  other vias: 71.59,62.54
N$139  (via drill 0.61 pad 1.78)
  other vias: 71.59,65.08
N$140  (via drill 0.61 pad 1.78)
  other vias: 71.59,67.62
N$141  (via drill 0.61 pad 1.78)
  other vias: 71.59,70.16
N$142  (via drill 0.61 pad 1.78)
  other vias: 71.59,72.7
N$143  (via drill 0.61 pad 1.78)
  other vias: 71.59,75.24
N$144  (via drill 0.61 pad 1.78)
  other vias: 71.59,77.78
N$145  (via drill 0.61 pad 1.78)
  other vias: 71.59,80.32
N$146  (via drill 0.61 pad 1.78)
  other vias: 71.59,82.86
N$147  (via drill 0.61 pad 1.78)
  other vias: 71.59,85.4
N$148  (via drill 0.61 pad 1.78)
  other vias: 74.13,82.86
N$149  (via drill 0.61 pad 1.78)
  other vias: 74.13,80.32
N$150  (via drill 0.61 pad 1.78)
  other vias: 74.13,77.78
N$151  (via drill 0.61 pad 1.78)
  other vias: 74.13,85.4
N$152  (via drill 0.61 pad 1.78)
  other vias: 74.13,75.24
N$153  (via drill 0.61 pad 1.78)
  other vias: 74.13,72.7
N$154  (via drill 0.61 pad 1.78)
  other vias: 74.13,70.16
N$155  (via drill 0.61 pad 1.78)
  other vias: 74.13,67.62
N$156  (via drill 0.61 pad 1.78)
  other vias: 74.13,65.08
N$157  (via drill 0.61 pad 1.78)
  other vias: 74.13,62.54
N$158  (via drill 0.61 pad 1.78)
  other vias: 76.67,62.54
N$159  (via drill 0.61 pad 1.78)
  other vias: 76.67,65.08
N$160  (via drill 0.61 pad 1.78)
  other vias: 76.67,67.62
N$161  (via drill 0.61 pad 1.78)
  other vias: 76.67,70.16
N$162  (via drill 0.61 pad 1.78)
  other vias: 76.67,72.7
N$163  (via drill 0.61 pad 1.78)
  other vias: 76.67,75.24
N$164  (via drill 0.61 pad 1.78)
  other vias: 76.67,77.78
N$165  (via drill 0.61 pad 1.78)
  other vias: 76.67,80.32
N$166  (via drill 0.61 pad 1.78)
  other vias: 76.67,82.86
N$167  (via drill 0.61 pad 1.78)
  other vias: 76.67,85.4
N$168  (via drill 0.61 pad 1.78)
  other vias: 79.21,85.4
N$169  (via drill 0.61 pad 1.78)
  other vias: 79.21,82.86
N$170  (via drill 0.61 pad 1.78)
  other vias: 79.21,80.32
N$171  (via drill 0.61 pad 1.78)
  other vias: 79.21,77.78
N$172  (via drill 0.61 pad 1.78)
  other vias: 79.21,75.24
N$173  (via drill 0.61 pad 1.78)
  other vias: 79.21,72.7
N$174  (via drill 0.61 pad 1.78)
  other vias: 79.21,70.16
N$175  (via drill 0.61 pad 1.78)
  other vias: 79.21,67.62
N$176  (via drill 0.61 pad 1.78)
  other vias: 79.21,65.08
N$177  (via drill 0.61 pad 1.78)
  other vias: 79.21,62.54
N$178  (via drill 0.61 pad 1.78)
  other vias: 81.75,62.54
N$179  (via drill 0.61 pad 1.78)
  other vias: 81.75,65.08
N$180  (via drill 0.61 pad 1.78)
  other vias: 81.75,67.62
N$181  (via drill 0.61 pad 1.78)
  other vias: 81.75,70.16
N$182  (via drill 0.61 pad 1.78)
  other vias: 81.75,72.7
N$183  (via drill 0.61 pad 1.78)
  other vias: 81.75,75.24
N$184  (via drill 0.61 pad 1.78)
  other vias: 81.75,77.78
N$185  (via drill 0.61 pad 1.78)
  other vias: 81.75,80.32
N$186  (via drill 0.61 pad 1.78)
  other vias: 81.75,82.86
N$187  (via drill 0.61 pad 1.78)
  other vias: 81.75,85.4
N$188  (via drill 0.61 pad 1.78)
  other vias: 89.37,82.86
N$189  (via drill 0.61 pad 1.78)
  other vias: 89.37,80.32
N$190  (via drill 0.61 pad 1.78)
  other vias: 89.37,77.78
N$191  (via drill 0.61 pad 1.78)
  other vias: 89.37,85.4
N$192  (via drill 0.61 pad 1.78)
  other vias: 89.37,75.24
N$193  (via drill 0.61 pad 1.78)
  other vias: 89.37,72.7
N$194  (via drill 0.61 pad 1.78)
  other vias: 89.37,70.16
N$195  (via drill 0.61 pad 1.78)
  other vias: 89.37,67.62
N$196  (via drill 0.61 pad 1.78)
  other vias: 89.37,65.08
N$197  (via drill 0.61 pad 1.78)
  other vias: 89.37,62.54
N$198  (via drill 0.61 pad 1.78)
  other vias: 91.91,62.54
N$199  (via drill 0.61 pad 1.78)
  other vias: 91.91,65.08
N$200  (via drill 0.61 pad 1.78)
  other vias: 91.91,67.62
N$201  (via drill 0.61 pad 1.78)
  other vias: 91.91,70.16
N$202  (via drill 0.61 pad 1.78)
  other vias: 91.91,72.7
N$203  (via drill 0.61 pad 1.78)
  other vias: 91.91,75.24
N$204  (via drill 0.61 pad 1.78)
  other vias: 91.91,77.78
N$205  (via drill 0.61 pad 1.78)
  other vias: 91.91,80.32
N$206  (via drill 0.61 pad 1.78)
  other vias: 91.91,82.86
N$207  (via drill 0.61 pad 1.78)
  other vias: 91.91,85.4
N$208  (via drill 0.61 pad 1.78)
  other vias: 94.45,85.4
N$209  (via drill 0.61 pad 1.78)
  other vias: 94.45,82.86
N$210  (via drill 0.61 pad 1.78)
  other vias: 94.45,80.32
N$211  (via drill 0.61 pad 1.78)
  other vias: 94.45,77.78
N$212  (via drill 0.61 pad 1.78)
  other vias: 94.45,75.24
N$213  (via drill 0.61 pad 1.78)
  other vias: 94.45,72.7
N$214  (via drill 0.61 pad 1.78)
  other vias: 94.45,70.16
N$215  (via drill 0.61 pad 1.78)
  other vias: 94.45,67.62
N$216  (via drill 0.61 pad 1.78)
  other vias: 94.45,65.08
N$217  (via drill 0.61 pad 1.78)
  other vias: 94.45,62.54
N$218  (via drill 0.61 pad 1.78)
  other vias: 96.99,62.54
N$219  (via drill 0.61 pad 1.78)
  other vias: 96.99,65.08
N$220  (via drill 0.61 pad 1.78)
  other vias: 96.99,67.62
N$221  (via drill 0.61 pad 1.78)
  other vias: 96.99,70.16
N$222  (via drill 0.61 pad 1.78)
  other vias: 96.99,72.7
N$223  (via drill 0.61 pad 1.78)
  other vias: 96.99,75.24
N$224  (via drill 0.61 pad 1.78)
  other vias: 96.99,77.78
N$225  (via drill 0.61 pad 1.78)
  other vias: 96.99,80.32
N$226  (via drill 0.61 pad 1.78)
  other vias: 96.99,82.86
N$227  (via drill 0.61 pad 1.78)
  other vias: 96.99,85.4
N$228  (via drill 0.61 pad 1.78)
  other vias: 84.29,82.86
N$229  (via drill 0.61 pad 1.78)
  other vias: 86.83,82.86
N$230  (via drill 0.61 pad 1.78)
  other vias: 86.83,80.32
N$231  (via drill 0.61 pad 1.78)
  other vias: 84.29,80.32
N$232  (via drill 0.61 pad 1.78)
  other vias: 84.29,77.78
N$233  (via drill 0.61 pad 1.78)
  other vias: 86.83,77.78
N$234  (via drill 0.61 pad 1.78)
  other vias: 86.83,75.24
N$235  (via drill 0.61 pad 1.78)
  other vias: 84.29,75.24
N$236  (via drill 0.61 pad 1.78)
  other vias: 84.29,72.7
N$237  (via drill 0.61 pad 1.78)
  other vias: 86.83,72.7
N$238  (via drill 0.61 pad 1.78)
  other vias: 86.83,70.16
N$239  (via drill 0.61 pad 1.78)
  other vias: 84.29,70.16
N$240  (via drill 0.61 pad 1.78)
  other vias: 84.29,67.62
N$241  (via drill 0.61 pad 1.78)
  other vias: 86.83,67.62
N$242  (via drill 0.61 pad 1.78)
  other vias: 86.83,65.08
N$243  (via drill 0.61 pad 1.78)
  other vias: 84.29,65.08
N$244  (via drill 0.61 pad 1.78)
  other vias: 84.29,62.54
N$245  (via drill 0.61 pad 1.78)
  other vias: 86.83,62.54
N$246  (via drill 0.61 pad 1.78)
  other vias: 53.81,108.26
N$247  (via drill 0.61 pad 1.78)
  other vias: 53.81,105.72
N$248  (via drill 0.61 pad 1.68)
  Bottom 0.406: 15.71,84.13 v15.71,148.9
N$249  (via drill 0.61 pad 1.78)
  other vias: 53.81,103.18
N$250  (via drill 0.61 pad 1.78)
  other vias: 53.81,110.8
N$251  (via drill 0.61 pad 1.78)
  other vias: 53.81,100.64
N$252  (via drill 0.61 pad 1.68)
  Bottom 0.406: 25.87,84.13 v25.87,148.9
N$253  (via drill 0.61 pad 1.68)
  Bottom 0.406: 28.41,84.13 v28.41,148.9
N$254  (via drill 0.61 pad 1.68)
  Bottom 0.406: 30.95,84.13 v30.95,148.9
N$255  (via drill 0.61 pad 1.68)
  Bottom 0.406: 33.49,84.13 v33.49,148.9
N$256  (via drill 0.61 pad 1.78)
  other vias: 53.81,98.1
N$257  (via drill 0.61 pad 1.78)
  other vias: 53.81,95.56
N$258  (via drill 0.61 pad 1.78)
  other vias: 53.81,93.02
N$259  (via drill 0.61 pad 1.78)
  other vias: 53.81,90.48
N$260  (via drill 0.61 pad 1.78)
  other vias: 53.81,87.94
N$261  (via drill 0.61 pad 1.78)
  other vias: 56.35,87.94
N$262  (via drill 0.61 pad 1.78)
  other vias: 56.35,90.48
N$263  (via drill 0.61 pad 1.78)
  other vias: 56.35,93.02
N$264  (via drill 0.61 pad 1.78)
  other vias: 56.35,95.56
N$265  (via drill 0.61 pad 1.78)
  other vias: 56.35,98.1
N$266  (via drill 0.61 pad 1.78)
  other vias: 56.35,100.64
N$267  (via drill 0.61 pad 1.78)
  other vias: 56.35,103.18
N$268  (via drill 0.61 pad 1.78)
  other vias: 56.35,105.72
N$269  (via drill 0.61 pad 1.78)
  other vias: 56.35,108.26
N$270  (via drill 0.61 pad 1.78)
  other vias: 56.35,110.8
N$271  (via drill 0.61 pad 1.78)
  other vias: 58.89,110.8
N$272  (via drill 0.61 pad 1.78)
  other vias: 58.89,108.26
N$273  (via drill 0.61 pad 1.78)
  other vias: 58.89,105.72
N$274  (via drill 0.61 pad 1.78)
  other vias: 58.89,103.18
N$275  (via drill 0.61 pad 1.78)
  other vias: 58.89,100.64
N$276  (via drill 0.61 pad 1.78)
  other vias: 58.89,98.1
N$277  (via drill 0.61 pad 1.78)
  other vias: 58.89,95.56
N$278  (via drill 0.61 pad 1.78)
  other vias: 58.89,93.02
N$279  (via drill 0.61 pad 1.78)
  other vias: 58.89,90.48
N$280  (via drill 0.61 pad 1.78)
  other vias: 58.89,87.94
N$281  (via drill 0.61 pad 1.78)
  other vias: 61.43,87.94
N$282  (via drill 0.61 pad 1.78)
  other vias: 61.43,90.48
N$283  (via drill 0.61 pad 1.78)
  other vias: 61.43,93.02
N$284  (via drill 0.61 pad 1.78)
  other vias: 61.43,95.56
N$285  (via drill 0.61 pad 1.78)
  other vias: 61.43,98.1
N$286  (via drill 0.61 pad 1.78)
  other vias: 61.43,100.64
N$287  (via drill 0.61 pad 1.78)
  other vias: 61.43,103.18
N$288  (via drill 0.61 pad 1.78)
  other vias: 61.43,105.72
N$289  (via drill 0.61 pad 1.78)
  other vias: 61.43,108.26
N$290  (via drill 0.61 pad 1.78)
  other vias: 61.43,110.8
N$291  (via drill 0.61 pad 1.78)
  other vias: 63.97,108.26
N$292  (via drill 0.61 pad 1.78)
  other vias: 63.97,105.72
N$293  (via drill 0.61 pad 1.78)
  other vias: 63.97,103.18
N$294  (via drill 0.61 pad 1.78)
  other vias: 63.97,110.8
N$295  (via drill 0.61 pad 1.78)
  other vias: 63.97,100.64
N$296  (via drill 0.61 pad 1.78)
  other vias: 63.97,98.1
N$297  (via drill 0.61 pad 1.78)
  other vias: 63.97,95.56
N$298  (via drill 0.61 pad 1.78)
  other vias: 63.97,93.02
N$299  (via drill 0.61 pad 1.78)
  other vias: 63.97,90.48
N$300  (via drill 0.61 pad 1.78)
  other vias: 63.97,87.94
N$301  (via drill 0.61 pad 1.78)
  other vias: 66.51,87.94
N$302  (via drill 0.61 pad 1.78)
  other vias: 66.51,90.48
N$303  (via drill 0.61 pad 1.78)
  other vias: 66.51,93.02
N$304  (via drill 0.61 pad 1.78)
  other vias: 66.51,95.56
N$305  (via drill 0.61 pad 1.78)
  other vias: 66.51,98.1
N$306  (via drill 0.61 pad 1.78)
  other vias: 66.51,100.64
N$307  (via drill 0.61 pad 1.78)
  other vias: 66.51,103.18
N$308  (via drill 0.61 pad 1.78)
  other vias: 66.51,105.72
N$309  (via drill 0.61 pad 1.78)
  other vias: 66.51,108.26
N$310  (via drill 0.61 pad 1.78)
  other vias: 66.51,110.8
N$311  (via drill 0.61 pad 1.78)
  other vias: 69.05,110.8
N$312  (via drill 0.61 pad 1.78)
  other vias: 69.05,108.26
N$313  (via drill 0.61 pad 1.78)
  other vias: 69.05,105.72
N$314  (via drill 0.61 pad 1.78)
  other vias: 69.05,103.18
N$315  (via drill 0.61 pad 1.78)
  other vias: 69.05,100.64
N$316  (via drill 0.61 pad 1.78)
  other vias: 69.05,98.1
N$317  (via drill 0.61 pad 1.78)
  other vias: 69.05,95.56
N$318  (via drill 0.61 pad 1.78)
  other vias: 69.05,93.02
N$319  (via drill 0.61 pad 1.78)
  other vias: 69.05,90.48
N$320  (via drill 0.61 pad 1.78)
  other vias: 69.05,87.94
N$321  (via drill 0.61 pad 1.78)
  other vias: 71.59,87.94
N$322  (via drill 0.61 pad 1.78)
  other vias: 71.59,90.48
N$323  (via drill 0.61 pad 1.78)
  other vias: 71.59,93.02
N$324  (via drill 0.61 pad 1.78)
  other vias: 71.59,95.56
N$325  (via drill 0.61 pad 1.78)
  other vias: 71.59,98.1
N$326  (via drill 0.61 pad 1.78)
  other vias: 71.59,100.64
N$327  (via drill 0.61 pad 1.78)
  other vias: 71.59,103.18
N$328  (via drill 0.61 pad 1.78)
  other vias: 71.59,105.72
N$329  (via drill 0.61 pad 1.78)
  other vias: 71.59,108.26
N$330  (via drill 0.61 pad 1.78)
  other vias: 71.59,110.8
N$331  (via drill 0.61 pad 1.78)
  other vias: 74.13,108.26
N$332  (via drill 0.61 pad 1.78)
  other vias: 74.13,105.72
N$333  (via drill 0.61 pad 1.78)
  other vias: 74.13,103.18
N$334  (via drill 0.61 pad 1.78)
  other vias: 74.13,110.8
N$335  (via drill 0.61 pad 1.78)
  other vias: 74.13,100.64
N$336  (via drill 0.61 pad 1.78)
  other vias: 74.13,98.1
N$337  (via drill 0.61 pad 1.78)
  other vias: 74.13,95.56
N$338  (via drill 0.61 pad 1.78)
  other vias: 74.13,93.02
N$339  (via drill 0.61 pad 1.78)
  other vias: 74.13,90.48
N$340  (via drill 0.61 pad 1.78)
  other vias: 74.13,87.94
N$341  (via drill 0.61 pad 1.78)
  other vias: 76.67,87.94
N$342  (via drill 0.61 pad 1.78)
  other vias: 76.67,90.48
N$343  (via drill 0.61 pad 1.78)
  other vias: 76.67,93.02
N$344  (via drill 0.61 pad 1.78)
  other vias: 76.67,95.56
N$345  (via drill 0.61 pad 1.78)
  other vias: 76.67,98.1
N$346  (via drill 0.61 pad 1.78)
  other vias: 76.67,100.64
N$347  (via drill 0.61 pad 1.78)
  other vias: 76.67,103.18
N$348  (via drill 0.61 pad 1.78)
  other vias: 76.67,105.72
N$349  (via drill 0.61 pad 1.78)
  other vias: 76.67,108.26
N$350  (via drill 0.61 pad 1.78)
  other vias: 76.67,110.8
N$351  (via drill 0.61 pad 1.78)
  other vias: 79.21,110.8
N$352  (via drill 0.61 pad 1.78)
  other vias: 79.21,108.26
N$353  (via drill 0.61 pad 1.78)
  other vias: 79.21,105.72
N$354  (via drill 0.61 pad 1.78)
  other vias: 79.21,103.18
N$355  (via drill 0.61 pad 1.78)
  other vias: 79.21,100.64
N$356  (via drill 0.61 pad 1.78)
  other vias: 79.21,98.1
N$357  (via drill 0.61 pad 1.78)
  other vias: 79.21,95.56
N$358  (via drill 0.61 pad 1.78)
  other vias: 79.21,93.02
N$359  (via drill 0.61 pad 1.78)
  other vias: 79.21,90.48
N$360  (via drill 0.61 pad 1.78)
  other vias: 79.21,87.94
N$361  (via drill 0.61 pad 1.78)
  other vias: 81.75,87.94
N$362  (via drill 0.61 pad 1.78)
  other vias: 81.75,90.48
N$363  (via drill 0.61 pad 1.78)
  other vias: 81.75,93.02
N$364  (via drill 0.61 pad 1.78)
  other vias: 81.75,95.56
N$365  (via drill 0.61 pad 1.78)
  other vias: 81.75,98.1
N$366  (via drill 0.61 pad 1.78)
  other vias: 81.75,100.64
N$367  (via drill 0.61 pad 1.78)
  other vias: 81.75,103.18
N$368  (via drill 0.61 pad 1.78)
  other vias: 81.75,105.72
N$369  (via drill 0.61 pad 1.78)
  other vias: 81.75,108.26
N$370  (via drill 0.61 pad 1.78)
  other vias: 81.75,110.8
N$371  (via drill 0.61 pad 1.78)
  other vias: 53.81,133.66
N$372  (via drill 0.61 pad 1.78)
  other vias: 53.81,131.12
N$373  (via drill 0.61 pad 1.78)
  other vias: 53.81,128.58
N$374  (via drill 0.61 pad 1.78)
  other vias: 53.81,136.2
N$375  (via drill 0.61 pad 1.78)
  other vias: 53.81,126.04
N$376  (via drill 0.61 pad 1.78)
  other vias: 53.81,123.5
N$377  (via drill 0.61 pad 1.78)
  other vias: 53.81,120.96
N$378  (via drill 0.61 pad 1.78)
  other vias: 53.81,118.42
N$379  (via drill 0.61 pad 1.78)
  other vias: 53.81,115.88
N$380  (via drill 0.61 pad 1.78)
  other vias: 53.81,113.34
N$381  (via drill 0.61 pad 1.78)
  other vias: 56.35,113.34
N$382  (via drill 0.61 pad 1.78)
  other vias: 56.35,115.88
N$383  (via drill 0.61 pad 1.78)
  other vias: 56.35,118.42
N$384  (via drill 0.61 pad 1.78)
  other vias: 56.35,120.96
N$385  (via drill 0.61 pad 1.78)
  other vias: 56.35,123.5
N$386  (via drill 0.61 pad 1.78)
  other vias: 56.35,126.04
N$387  (via drill 0.61 pad 1.78)
  other vias: 56.35,128.58
N$388  (via drill 0.61 pad 1.78)
  other vias: 56.35,131.12
N$389  (via drill 0.61 pad 1.78)
  other vias: 56.35,133.66
N$390  (via drill 0.61 pad 1.78)
  other vias: 56.35,136.2
N$391  (via drill 0.61 pad 1.78)
  other vias: 58.89,136.2
N$392  (via drill 0.61 pad 1.78)
  other vias: 58.89,133.66
N$393  (via drill 0.61 pad 1.78)
  other vias: 58.89,131.12
N$394  (via drill 0.61 pad 1.78)
  other vias: 58.89,128.58
N$395  (via drill 0.61 pad 1.78)
  other vias: 58.89,126.04
N$396  (via drill 0.61 pad 1.78)
  other vias: 58.89,123.5
N$397  (via drill 0.61 pad 1.78)
  other vias: 58.89,120.96
N$398  (via drill 0.61 pad 1.78)
  other vias: 58.89,118.42
N$399  (via drill 0.61 pad 1.78)
  other vias: 58.89,115.88
N$400  (via drill 0.61 pad 1.78)
  other vias: 58.89,113.34
N$401  (via drill 0.61 pad 1.78)
  other vias: 61.43,113.34
N$402  (via drill 0.61 pad 1.78)
  other vias: 61.43,115.88
N$403  (via drill 0.61 pad 1.78)
  other vias: 61.43,118.42
N$404  (via drill 0.61 pad 1.78)
  other vias: 61.43,120.96
N$405  (via drill 0.61 pad 1.78)
  other vias: 61.43,123.5
N$406  (via drill 0.61 pad 1.78)
  other vias: 61.43,126.04
N$407  (via drill 0.61 pad 1.78)
  other vias: 61.43,128.58
N$408  (via drill 0.61 pad 1.78)
  other vias: 61.43,131.12
N$409  (via drill 0.61 pad 1.78)
  other vias: 61.43,133.66
N$410  (via drill 0.61 pad 1.78)
  other vias: 61.43,136.2
N$411  (via drill 0.61 pad 1.78)
  other vias: 63.97,133.66
N$412  (via drill 0.61 pad 1.78)
  other vias: 63.97,131.12
N$413  (via drill 0.61 pad 1.78)
  other vias: 63.97,128.58
N$414  (via drill 0.61 pad 1.78)
  other vias: 63.97,136.2
N$415  (via drill 0.61 pad 1.78)
  other vias: 63.97,126.04
N$416  (via drill 0.61 pad 1.78)
  other vias: 63.97,123.5
N$417  (via drill 0.61 pad 1.78)
  other vias: 63.97,120.96
N$418  (via drill 0.61 pad 1.78)
  other vias: 63.97,118.42
N$419  (via drill 0.61 pad 1.78)
  other vias: 63.97,115.88
N$420  (via drill 0.61 pad 1.78)
  other vias: 63.97,113.34
N$421  (via drill 0.61 pad 1.78)
  other vias: 66.51,113.34
N$422  (via drill 0.61 pad 1.78)
  other vias: 66.51,115.88
N$423  (via drill 0.61 pad 1.78)
  other vias: 66.51,118.42
N$424  (via drill 0.61 pad 1.78)
  other vias: 66.51,120.96
N$425  (via drill 0.61 pad 1.78)
  other vias: 66.51,123.5
N$426  (via drill 0.61 pad 1.78)
  other vias: 66.51,126.04
N$427  (via drill 0.61 pad 1.78)
  other vias: 66.51,128.58
N$428  (via drill 0.61 pad 1.78)
  other vias: 66.51,131.12
N$429  (via drill 0.61 pad 1.78)
  other vias: 66.51,133.66
N$430  (via drill 0.61 pad 1.78)
  other vias: 66.51,136.2
N$431  (via drill 0.61 pad 1.78)
  other vias: 69.05,136.2
N$432  (via drill 0.61 pad 1.78)
  other vias: 69.05,133.66
N$433  (via drill 0.61 pad 1.78)
  other vias: 69.05,131.12
N$434  (via drill 0.61 pad 1.78)
  other vias: 69.05,128.58
N$435  (via drill 0.61 pad 1.78)
  other vias: 69.05,126.04
N$436  (via drill 0.61 pad 1.78)
  other vias: 69.05,123.5
N$437  (via drill 0.61 pad 1.78)
  other vias: 69.05,120.96
N$438  (via drill 0.61 pad 1.78)
  other vias: 69.05,118.42
N$439  (via drill 0.61 pad 1.78)
  other vias: 69.05,115.88
N$440  (via drill 0.61 pad 1.78)
  other vias: 69.05,113.34
N$441  (via drill 0.61 pad 1.78)
  other vias: 71.59,113.34
N$442  (via drill 0.61 pad 1.78)
  other vias: 71.59,115.88
N$443  (via drill 0.61 pad 1.78)
  other vias: 71.59,118.42
N$444  (via drill 0.61 pad 1.78)
  other vias: 71.59,120.96
N$445  (via drill 0.61 pad 1.78)
  other vias: 71.59,123.5
N$446  (via drill 0.61 pad 1.78)
  other vias: 71.59,126.04
N$447  (via drill 0.61 pad 1.78)
  other vias: 71.59,128.58
N$448  (via drill 0.61 pad 1.78)
  other vias: 71.59,131.12
N$449  (via drill 0.61 pad 1.78)
  other vias: 71.59,133.66
N$450  (via drill 0.61 pad 1.78)
  other vias: 71.59,136.2
N$451  (via drill 0.61 pad 1.78)
  other vias: 74.13,133.66
N$452  (via drill 0.61 pad 1.78)
  other vias: 74.13,131.12
N$453  (via drill 0.61 pad 1.78)
  other vias: 74.13,128.58
N$454  (via drill 0.61 pad 1.78)
  other vias: 74.13,136.2
N$455  (via drill 0.61 pad 1.78)
  other vias: 74.13,126.04
N$456  (via drill 0.61 pad 1.78)
  other vias: 74.13,123.5
N$457  (via drill 0.61 pad 1.78)
  other vias: 74.13,120.96
N$458  (via drill 0.61 pad 1.78)
  other vias: 74.13,118.42
N$459  (via drill 0.61 pad 1.78)
  other vias: 74.13,115.88
N$460  (via drill 0.61 pad 1.78)
  other vias: 74.13,113.34
N$461  (via drill 0.61 pad 1.78)
  other vias: 76.67,113.34
N$462  (via drill 0.61 pad 1.78)
  other vias: 76.67,115.88
N$463  (via drill 0.61 pad 1.78)
  other vias: 76.67,118.42
N$464  (via drill 0.61 pad 1.78)
  other vias: 76.67,120.96
N$465  (via drill 0.61 pad 1.78)
  other vias: 76.67,123.5
N$466  (via drill 0.61 pad 1.78)
  other vias: 76.67,126.04
N$467  (via drill 0.61 pad 1.78)
  other vias: 76.67,128.58
N$468  (via drill 0.61 pad 1.78)
  other vias: 76.67,131.12
N$469  (via drill 0.61 pad 1.78)
  other vias: 76.67,133.66
N$470  (via drill 0.61 pad 1.78)
  other vias: 76.67,136.2
N$471  (via drill 0.61 pad 1.78)
  other vias: 79.21,136.2
N$472  (via drill 0.61 pad 1.78)
  other vias: 79.21,133.66
N$473  (via drill 0.61 pad 1.78)
  other vias: 79.21,131.12
N$474  (via drill 0.61 pad 1.78)
  other vias: 79.21,128.58
N$475  (via drill 0.61 pad 1.78)
  other vias: 79.21,126.04
N$476  (via drill 0.61 pad 1.78)
  other vias: 79.21,123.5
N$477  (via drill 0.61 pad 1.78)
  other vias: 79.21,120.96
N$478  (via drill 0.61 pad 1.78)
  other vias: 79.21,118.42
N$479  (via drill 0.61 pad 1.78)
  other vias: 79.21,115.88
N$480  (via drill 0.61 pad 1.78)
  other vias: 79.21,113.34
N$481  (via drill 0.61 pad 1.78)
  other vias: 81.75,113.34
N$482  (via drill 0.61 pad 1.78)
  other vias: 81.75,115.88
N$483  (via drill 0.61 pad 1.78)
  other vias: 81.75,118.42
N$484  (via drill 0.61 pad 1.78)
  other vias: 81.75,120.96
N$485  (via drill 0.61 pad 1.78)
  other vias: 81.75,123.5
N$486  (via drill 0.61 pad 1.78)
  other vias: 81.75,126.04
N$487  (via drill 0.61 pad 1.78)
  other vias: 81.75,128.58
N$488  (via drill 0.61 pad 1.78)
  other vias: 81.75,131.12
N$489  (via drill 0.61 pad 1.78)
  other vias: 81.75,133.66
N$490  (via drill 0.61 pad 1.78)
  other vias: 81.75,136.2
N$491  (via drill 0.61 pad 1.78)
  other vias: 84.29,103.18
N$492  (via drill 0.61 pad 1.78)
  other vias: 84.29,100.64
N$493  (via drill 0.61 pad 1.78)
  other vias: 84.29,98.1
N$494  (via drill 0.61 pad 1.78)
  other vias: 84.29,95.56
N$495  (via drill 0.61 pad 1.78)
  other vias: 84.29,93.02
N$496  (via drill 0.61 pad 1.78)
  other vias: 84.29,90.48
N$497  (via drill 0.61 pad 1.78)
  other vias: 84.29,87.94
N$498  (via drill 0.61 pad 1.78)
  other vias: 86.83,87.94
N$499  (via drill 0.61 pad 1.78)
  other vias: 86.83,90.48
N$500  (via drill 0.61 pad 1.78)
  other vias: 86.83,93.02
N$501  (via drill 0.61 pad 1.78)
  other vias: 86.83,95.56
N$502  (via drill 0.61 pad 1.78)
  other vias: 86.83,98.1
N$503  (via drill 0.61 pad 1.78)
  other vias: 86.83,100.64
N$504  (via drill 0.61 pad 1.78)
  other vias: 86.83,103.18
N$505  (via drill 0.61 pad 1.78)
  other vias: 89.37,100.64
N$506  (via drill 0.61 pad 1.78)
  other vias: 89.37,98.1
N$507  (via drill 0.61 pad 1.78)
  other vias: 89.37,95.56
N$508  (via drill 0.61 pad 1.78)
  other vias: 89.37,103.18
N$509  (via drill 0.61 pad 1.78)
  other vias: 89.37,93.02
N$510  (via drill 0.61 pad 1.78)
  other vias: 89.37,90.48
N$511  (via drill 0.61 pad 1.78)
  other vias: 89.37,87.94
N$512  (via drill 0.61 pad 1.78)
  other vias: 91.91,87.94
N$513  (via drill 0.61 pad 1.78)
  other vias: 91.91,90.48
N$514  (via drill 0.61 pad 1.78)
  other vias: 91.91,93.02
N$515  (via drill 0.61 pad 1.78)
  other vias: 91.91,95.56
N$516  (via drill 0.61 pad 1.78)
  other vias: 91.91,98.1
N$517  (via drill 0.61 pad 1.78)
  other vias: 91.91,100.64
N$518  (via drill 0.61 pad 1.78)
  other vias: 91.91,103.18
N$519  (via drill 0.61 pad 1.78)
  other vias: 94.45,103.18
N$520  (via drill 0.61 pad 1.78)
  other vias: 94.45,100.64
N$521  (via drill 0.61 pad 1.78)
  other vias: 94.45,98.1
N$522  (via drill 0.61 pad 1.78)
  other vias: 94.45,95.56
N$523  (via drill 0.61 pad 1.78)
  other vias: 94.45,93.02
N$524  (via drill 0.61 pad 1.78)
  other vias: 94.45,90.48
N$525  (via drill 0.61 pad 1.78)
  other vias: 94.45,87.94
N$526  (via drill 0.61 pad 1.78)
  other vias: 96.99,87.94
N$527  (via drill 0.61 pad 1.78)
  other vias: 96.99,90.48
N$528  (via drill 0.61 pad 1.78)
  other vias: 96.99,93.02
N$529  (via drill 0.61 pad 1.78)
  other vias: 96.99,95.56
N$530  (via drill 0.61 pad 1.78)
  other vias: 96.99,98.1
N$531  (via drill 0.61 pad 1.78)
  other vias: 96.99,100.64
N$532  (via drill 0.61 pad 1.78)
  other vias: 96.99,103.18
N$533  (via drill 0.61 pad 1.78)
  other vias: 84.29,128.58
N$534  (via drill 0.61 pad 1.78)
  other vias: 84.29,126.04
N$535  (via drill 0.61 pad 1.78)
  other vias: 84.29,123.5
N$536  (via drill 0.61 pad 1.78)
  other vias: 84.29,120.96
N$537  (via drill 0.61 pad 1.78)
  other vias: 84.29,118.42
N$538  (via drill 0.61 pad 1.78)
  other vias: 84.29,115.88
N$539  (via drill 0.61 pad 1.78)
  other vias: 84.29,113.34
N$540  (via drill 0.61 pad 1.78)
  other vias: 84.29,110.8
N$541  (via drill 0.61 pad 1.78)
  other vias: 84.29,108.26
N$542  (via drill 0.61 pad 1.78)
  other vias: 84.29,105.72
N$543  (via drill 0.61 pad 1.78)
  other vias: 86.83,105.72
N$544  (via drill 0.61 pad 1.78)
  other vias: 86.83,108.26
N$545  (via drill 0.61 pad 1.78)
  other vias: 86.83,110.8
N$546  (via drill 0.61 pad 1.78)
  other vias: 86.83,113.34
N$547  (via drill 0.61 pad 1.78)
  other vias: 86.83,115.88
N$548  (via drill 0.61 pad 1.78)
  other vias: 86.83,118.42
N$549  (via drill 0.61 pad 1.78)
  other vias: 86.83,120.96
N$550  (via drill 0.61 pad 1.78)
  other vias: 86.83,123.5
N$551  (via drill 0.61 pad 1.78)
  other vias: 86.83,126.04
N$552  (via drill 0.61 pad 1.78)
  other vias: 86.83,128.58
N$553  (via drill 0.61 pad 1.78)
  other vias: 89.37,126.04
N$554  (via drill 0.61 pad 1.78)
  other vias: 89.37,123.5
N$555  (via drill 0.61 pad 1.78)
  other vias: 89.37,120.96
N$556  (via drill 0.61 pad 1.78)
  other vias: 89.37,128.58
N$557  (via drill 0.61 pad 1.78)
  other vias: 89.37,118.42
N$558  (via drill 0.61 pad 1.78)
  other vias: 89.37,115.88
N$559  (via drill 0.61 pad 1.78)
  other vias: 89.37,113.34
N$560  (via drill 0.61 pad 1.78)
  other vias: 89.37,110.8
N$561  (via drill 0.61 pad 1.78)
  other vias: 89.37,108.26
N$562  (via drill 0.61 pad 1.78)
  other vias: 89.37,105.72
N$563  (via drill 0.61 pad 1.78)
  other vias: 91.91,105.72
N$564  (via drill 0.61 pad 1.78)
  other vias: 91.91,108.26
N$565  (via drill 0.61 pad 1.78)
  other vias: 91.91,110.8
N$566  (via drill 0.61 pad 1.78)
  other vias: 91.91,113.34
N$567  (via drill 0.61 pad 1.78)
  other vias: 91.91,115.88
N$568  (via drill 0.61 pad 1.78)
  other vias: 91.91,118.42
N$569  (via drill 0.61 pad 1.78)
  other vias: 91.91,120.96
N$570  (via drill 0.61 pad 1.78)
  other vias: 91.91,123.5
N$571  (via drill 0.61 pad 1.78)
  other vias: 91.91,126.04
N$572  (via drill 0.61 pad 1.78)
  other vias: 91.91,128.58
N$573  (via drill 0.61 pad 1.78)
  other vias: 94.45,128.58
N$574  (via drill 0.61 pad 1.78)
  other vias: 94.45,126.04
N$575  (via drill 0.61 pad 1.78)
  other vias: 94.45,123.5
N$576  (via drill 0.61 pad 1.78)
  other vias: 94.45,120.96
N$577  (via drill 0.61 pad 1.78)
  other vias: 94.45,118.42
N$578  (via drill 0.61 pad 1.78)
